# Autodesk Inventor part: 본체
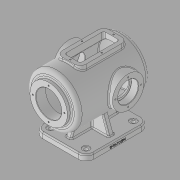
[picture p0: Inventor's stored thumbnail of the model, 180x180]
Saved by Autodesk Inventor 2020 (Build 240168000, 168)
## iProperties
Created: 2021-11
Part Number: 본체
Material: 일반
Document SubType Name: Modeling
Designer: Administrator
Density: 1 g/cm^3
Appearance: 기본값
Mass: 1311.09 g
Surface Area: 2405.55 cm^2
Volume: 1311.09 cm^3
Author: Administrator
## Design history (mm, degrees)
sketch "스케치1"
  geometry: L1 (-80, -65)-(80, -65); L2 (80, -65)-(80, 65); L3 (80, 65)-(-80, 65); L4 (-80, 65)-(-80, -65); L5 (-80, -65)-(80, 65); L6 (80, -65)-(-80, 65); 1 further point
  constraints: 12 end point, 2 midpoint, 2 parallel, 1 horizontal, 1 perpendicular
  dimensions: "d0" = 160 distance of L3.end L2.end; "d1" = 130 distance of L2.end L1.end
extrude "돌출1" new body sketch "스케치1" distance "d2" = 14; taper "d3" = 0 deg
sketch "스케치2"
  geometry: L1 (110, 114)-(110, 161.5); L2 (110, 161.5)-(100, 161.5); L3 (100, 161.5)-(100, 179); L4 (100, 179)-(-75.993, 179); L5 (110, 114)-(-100, 114); L6 (80, 0)-(80, 14) reference; A1 r 100 centre (0, 114) between (-75.993, 179) and (-100, 114); 1 further point
  constraints: 10 end point, 3 perpendicular, 2 point on circle, 1 centre point, 1 horizontal, 1 horizontal alignment, 1 vertical
  dimensions: "d6" = 114 vertical distance of point (0, 0) L1.start; "d7" = 95 diameter of L2 L5; "d8" = 130 diameter of L4 L5; "d9" = 210 distance from line of L5.end L1; "d10" = 10 distance of L1.end L2.end; "d11" = 30 distance between parallel lines of L1 L6; "d13" = 100 distance of L5.end A1.centre
revolve "회전1" sketch "스케치2" stored, may be unused: angle "d14" = 90 deg
sketch "스케치3"
  geometry: L1 (110, 66.5)-(110, 161.5) reference; L2 (110, 146.5)-(85, 146.5); L3 (85, 146.5)-(85, 169); L4 (85, 169)-(-71.239, 169); L5 (-90, 114)-(110, 114); L6 (110, 146.5)-(110, 114); A1 r 100 centre (0, 114) between (-75.993, 179) and (-75.993, 49) reference; A2 r 90 centre (0, 114) between (-71.239, 169) and (-90, 114); 1 further point
  constraints: 10 end point, 4 perpendicular, 2 point on circle, 1 centre point, 1 midpoint, 1 point on line
  dimensions: "d15" = 10 radial gap between concentric circles of A1 A2; "d16" = 25 distance of L2.start L2.end; "d17" = 65 diameter of L2 L5; "d18" = 110 diameter of L4 L5
revolve "회전2" sketch "스케치3" stored, may be unused: angle "d19" = 90 deg
sketch "스케치4"
  geometry: L1 (-7, -7)-(7, -7); L2 (7, -7)-(7, 7); L3 (7, 7)-(-7, 7); L4 (-7, 7)-(-7, -7); L5 (-7, -7)-(7, 7); L6 (7, -7)-(-7, 7); 1 further point
  constraints: 12 end point, 2 midpoint, 2 parallel, 1 horizontal, 1 perpendicular
  dimensions: "d20" = 14 distance of L3.end L2.end; "d21" = 14 distance of L2.end L1.end
extrude "돌출2" join sketch "스케치4" stored distance "d22" = 14; taper "d23" = 0 deg
sketch "스케치5"
  geometry: L1 (-80, 14)-(80, 14) reference; L2 (60, 14)-(48.698, 45.052); 1 further point
  constraints: 2 end point, 1 point on line
  dimensions: "d24" = 110 deg angle of L1 L2; "d25" = 60 horizontal distance of point (0, 0) L2.start
feature "리브1" sketch "스케치5" dims "d26" = 1, "d27" = 14, "d28" = 0, "d29" = 0, "d30" = 1, "d31" = 1
sketch "스케치6"
  geometry: L1 (-65, 14)-(65, 14) reference; L2 (50, 14)-(38.446, 45.744); 1 further point
  constraints: 2 end point, 1 point on line
  dimensions: "d32" = 110 deg angle of L1 L2; "d33" = 50 horizontal distance of point (0, 0) L2.start
feature "리브2" sketch "스케치6" dims "d34" = 1, "d35" = 14, "d36" = 0, "d37" = 0, "d38" = 1, "d39" = 1
node "작업 평면1"
sketch "스케치7"
  geometry: L1 (-45, 30)-(45, 30); L2 (60, 15)-(60, -15); L3 (45, -30)-(-45, -30); L4 (-60, -15)-(-60, 15); L5 (-110, 47.5)-(-110, -47.5) reference; A1 r 15 centre (-45, 15) between (-45, 30) and (-60, 15); A2 r 15 centre (45, 15) between (60, 15) and (45, 30); A3 r 15 centre (45, -15) between (45, -30) and (60, -15); A4 r 15 centre (-45, -15) between (-60, -15) and (-45, -30); 6 further points
  constraints: 8 end point, 8 point on circle, 8 point on line, 8 tangent, 4 centre point, 3 equal radius, 2 parallel, 1 horizontal, 1 horizontal alignment, 1 midpoint, 1 perpendicular
  dimensions: "d41" = 60 distance of point (60, 30) point (60, -30); "d42" = 120 distance of point (-60, 30) point (60, 30); "d43" = 50 distance between parallel lines of L4 L5; "d46" = 15 radius of A1
extrude "돌출3" join sketch "스케치7" stored distance "d44" = 14; taper "d45" = 0 deg
sketch "스케치8"
  geometry: L1 (60, -15)-(60, 15) reference; L2 (45, 30)-(-45, 30) reference; L3 (-60, 15)-(-60, -15) reference; L4 (-45, -30)-(45, -30) reference; L5 (-45, 20)-(45, 20); L6 (50, 15)-(50, -15); L7 (45, -20)-(-45, -20); L8 (-50, -15)-(-50, 15); A1 r 15 centre (45, 15) between (60, 15) and (45, 30) reference; A2 r 15 centre (-45, 15) between (-45, 30) and (-60, 15) reference; A3 r 15 centre (-45, -15) between (-60, -15) and (-45, -30) reference; A4 r 15 centre (45, -15) between (45, -30) and (60, -15) reference; A5 r 5 centre (45, 15) between (50, 15) and (45, 20); A6 r 5 centre (45, -15) between (45, -20) and (50, -15); A7 r 5 centre (-45, -15) between (-50, -15) and (-45, -20); A8 r 5 centre (-45, 15) between (-45, 20) and (-50, 15); 1 further point
  constraints: 8 end point, 8 point on circle, 4 centre point, 7 other
  dimensions: "d47" = 10 distance between parallel lines of L2 L5
extrude "돌출4" cut sketch "스케치8" stored distance "d48" = 14; taper "d49" = 0 deg
node "작업 평면2"
sketch "스케치9"
  geometry: L1 (-110, 161.5)-(-110, 66.5) reference; C1 r 40 at (17, 114); 2 further points
  constraints: 1 centre point, 1 horizontal alignment, 1 midpoint
  dimensions: "d51" = 127 distance from line of C1.centre L1; "d52" = 80 diameter of C1
extrude "돌출5" join sketch "스케치9" stored distance "d53" = 14; taper "d54" = 0 deg
sketch "스케치10"
  geometry: C1 r 40 at (0, 0) reference; 2 further points
  constraints: 1 coincident
hole "구멍1" sketch "스케치10" at (0, 0) diameter "d55" = 42; stored, may be unused: countersink angle "d59" = 90 deg, drill point angle "d61" = 0 deg; dims "d56" = 6, "d57" = 52, "d58" = 18, "d60" = 8
sketch "스케치11" dims "d62" = 65
  geometry: L1 (0, 0)-(0, 32.5); C1 r 26 at (0, 0) reference; 2 further points
  constraints: 2 coincident, 2 end point, 1 vertical, 1 vertical alignment, 2 other
hole "구멍2" sketch "스케치11" at (0, 32.5) diameter "d63" = 3.45873; stored, may be unused: countersink angle "d67" = 90 deg, drill point angle "d69" = 118 deg; dims "d64" = 11, "d65" = 52, "d66" = 18, "d68" = 13
sketch "스케치12" dims "d73" = 80
  geometry: L1 (0, 0)-(40, 0); C1 r 32.5 at (0, 0) reference; 2 further points
  constraints: 2 coincident, 2 end point, 1 horizontal, 1 horizontal alignment, 2 other
hole "구멍3" sketch "스케치12" at (40, 0) diameter "d74" = 3.45873; stored, may be unused: countersink angle "d78" = 90 deg, drill point angle "d80" = 118 deg; dims "d75" = 11, "d76" = 52, "d77" = 18, "d79" = 13
sketch "스케치13"
  geometry: L1 (0, 25)-(0, -25); L2 (-55, 0)-(55, 0); 6 further points
  constraints: 6 coincident, 4 end point, 2 midpoint, 1 horizontal, 1 vertical
  dimensions: "d84" = 50 distance of L1.start L1.end; "d85" = 110 distance of L2.start L2.end
hole "구멍4" sketch "스케치13" at (0, 25), (0, -25), (-55, 0), (55, 0) diameter "d86" = 3.45873; stored, may be unused: countersink angle "d90" = 90 deg, drill point angle "d92" = 118 deg; dims "d87" = 9, "d88" = 52, "d89" = 18, "d91" = 11
fillet "모깎기1" dims "d93" = 20
sketch "스케치14"
  geometry: A1 r 20 centre (-60, -45) between (-80, -45) and (-60, -65) reference; A2 r 20 centre (60, -45) between (60, -65) and (80, -45) reference; A3 r 20 centre (60, 45) between (80, 45) and (60, 65) reference; A4 r 20 centre (-60, 45) between (-60, 65) and (-80, 45) reference; 5 further points
  constraints: 4 coincident
hole "구멍5" sketch "스케치14" at (-60, -45), (60, -45), (60, 45), (-60, 45) diameter "d94" = 9; stored, may be unused: countersink angle "d98" = 90 deg, drill point angle "d100" = 0 deg; dims "d95" = 9, "d96" = 18, "d97" = 2, "d99" = 11
fillet "모깎기2" dims "d101" = 10
fillet "모깎기3" dims "d102" = 0.3
fillet "모깎기4" dims "d103" = 3
fillet "모깎기5" dims "d104" = 3
fillet "모깎기6" dims "d105" = 3
chamfer "모따기1" distance "d106" = 1; stored, may be unused: second distance "d107" = 2, angle "d108" = 45 deg
sketch "스케치15"
  geometry: L1 (41.583, 8.002)-(78.417, 8.002); L2 (78.417, 8.002)-(78.417, 1.998); L3 (78.417, 1.998)-(41.583, 1.998); L4 (41.583, 1.998)-(41.583, 8.002); L5 (0, 0)-(120, 0) reference; 4 further points
  constraints: 3 midpoint, 1 vertical alignment, 2 other
  dimensions: "d109" = 5 distance from line of L5 point (41.583, 5)
feature "엠보싱1" sketch "스케치15" dims "d0" = 160, "d1" = 130, "d110" = 0.5, "d111" = 0
node "솔리드1"
mirror "미러1"
mirror "미러2"
pattern_circular "원형 패턴1" dims angle "d71" = 360 deg
mirror "미러3"
pattern_circular "원형 패턴2" dims angle "d82" = 360 deg
node "투영된 루프1"
feature "A9D066F2-1C7D-4E18-AEED-F7BC21143FA4" dims "d94" = 9, "d95" = 9, "d96" = 18, "d97" = 2, "d98" = 90 deg, "d99" = 11, "d100" = 0
other parameters: "d40" = 184, "d50" = -75
